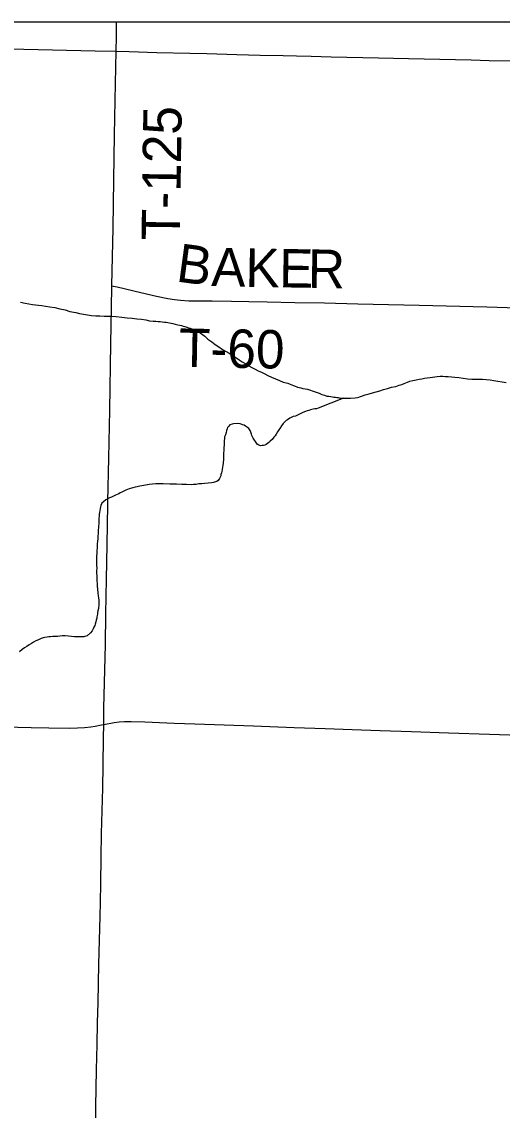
# Model space of a CAD drawing. Extents: x 2.1 to 73.9, y 4 to 26.
# Drawn here: x 43.618 to 43.974, y 24.1 to 24.905 of the extents above; entities that cross this region are included whole.
import ezdxf

# ---------------------------------------------------------------- set-up
doc = ezdxf.new("R2010")
doc.units = 0
for name, color, linetype in [('GM_X_County_Road', 7, 'Continuous'), ('GM_X_Minor_River', 7, 'Continuous'), ('GM_X_Township_Road', 7, 'Continuous'), ('GM_X_Township_Road_Text', 7, 'Continuous'), ('SH_Data', 7, 'Continuous')]:
    doc.layers.add(name, color=color, linetype=linetype)

msp = doc.modelspace()

# ---------------------------------------------------------------- linework, layer by layer
at = {"layer": 'GM_X_County_Road'}
for points in [[(43.16489, 24.39352), (43.19852, 24.39287), (43.21842, 24.39249), (43.24172, 24.39197), (43.25913, 24.3915), (43.2986, 24.39047), (43.31693, 24.39001), (43.36697, 24.38903), (43.40551, 24.38816), (43.44528, 24.38729), (43.47978, 24.38654), (43.4975, 24.38626), (43.53915, 24.38537), (43.60565, 24.38389), (43.62554, 24.3835), (43.6386, 24.38326), (43.65351, 24.38296), (43.65971, 24.38304), (43.66496, 24.38332), (43.66957, 24.38379), (43.67292, 24.38436), (43.67746, 24.38531), (43.67911, 24.38566)], [(43.67911, 24.38566), (43.68693, 24.38705), (43.69061, 24.38748), (43.69462, 24.38771), (43.69957, 24.38775), (43.70951, 24.38754), (43.73125, 24.38671), (43.74648, 24.3862), (43.78996, 24.38451), (43.8201, 24.38351), (43.84309, 24.38263), (43.86297, 24.38194), (43.88378, 24.38119), (43.90708, 24.38035), (43.93443, 24.37951), (43.96487, 24.37841), (44.00175, 24.37712), (44.04068, 24.37576), (44.05496, 24.37523), (44.07206, 24.37468), (44.0938, 24.3739), (44.13543, 24.37248), (44.17551, 24.37109), (44.18536, 24.37079)]]:
    msp.add_lwpolyline(points, dxfattribs=at)
at = {"layer": 'GM_X_Minor_River'}
for points in [[(43.61753, 24.69783), (43.62094, 24.6972), (43.62378, 24.69659), (43.62644, 24.69617), (43.62872, 24.69575), (43.6308, 24.69552), (43.63327, 24.6953), (43.63593, 24.69487), (43.63934, 24.69444), (43.64295, 24.69381), (43.64674, 24.69299), (43.65053, 24.69217), (43.65393, 24.69097), (43.65849, 24.69014), (43.66133, 24.68953), (43.66417, 24.68891), (43.66702, 24.68848), (43.67005, 24.68806), (43.67328, 24.68781), (43.67632, 24.68777), (43.67936, 24.68753), (43.68222, 24.68748), (43.68526, 24.68743), (43.6883, 24.68719), (43.69266, 24.68674), (43.69646, 24.6863), (43.70026, 24.68605), (43.70368, 24.68562), (43.70709, 24.68518), (43.71032, 24.68475), (43.71297, 24.68414), (43.71563, 24.6839), (43.71772, 24.68387), (43.71943, 24.68365), (43.72095, 24.68344), (43.72247, 24.68322), (43.72417, 24.68301), (43.72532, 24.68299), (43.73024, 24.68196), (43.73214, 24.68155), (43.73403, 24.68114), (43.73555, 24.68092), (43.73669, 24.68053), (43.73801, 24.68012), (43.73915, 24.67992), (43.74066, 24.67932), (43.7418, 24.67892), (43.74312, 24.67852), (43.74426, 24.67812), (43.74539, 24.67773), (43.74671, 24.67714), (43.74785, 24.67655), (43.74917, 24.67596), (43.75049, 24.67517), (43.75218, 24.67401), (43.75406, 24.67265), (43.75612, 24.67052), (43.75913, 24.66857), (43.76157, 24.66664), (43.7644, 24.66488), (43.76703, 24.66294), (43.76967, 24.66138), (43.77212, 24.66001), (43.774, 24.65884), (43.77569, 24.65767), (43.77758, 24.6565), (43.77946, 24.65514), (43.78153, 24.65378), (43.78436, 24.65221), (43.78662, 24.65084), (43.78888, 24.64948), (43.79114, 24.6483), (43.79359, 24.64712), (43.79586, 24.64613), (43.79831, 24.64477), (43.80076, 24.64359), (43.80341, 24.6424), (43.80624, 24.64103), (43.80926, 24.63984), (43.8121, 24.63865), (43.81551, 24.63784), (43.81777, 24.63685), (43.82042, 24.63586), (43.82269, 24.63506), (43.82496, 24.63446), (43.82667, 24.63405), (43.82837, 24.63364), (43.82989, 24.63343)], [(43.82989, 24.63343), (43.83576, 24.63162), (43.83859, 24.63044), (43.84067, 24.62964), (43.84256, 24.62904), (43.84427, 24.62845), (43.84579, 24.62823), (43.8473, 24.62802), (43.84844, 24.62781), (43.84958, 24.6276), (43.85072, 24.62758), (43.85167, 24.62738), (43.85262, 24.62736), (43.85357, 24.62716), (43.85489, 24.62695), (43.8566, 24.62692), (43.85775, 24.6269), (43.85908, 24.62688), (43.86022, 24.62686), (43.86193, 24.62683), (43.86536, 24.62716), (43.86707, 24.62732), (43.86803, 24.62768), (43.86917, 24.62805), (43.8707, 24.62859), (43.87262, 24.62932), (43.87567, 24.63003), (43.87816, 24.63075), (43.88083, 24.63166), (43.88351, 24.63237), (43.88618, 24.63328), (43.88924, 24.63399), (43.89229, 24.63489), (43.89535, 24.6356), (43.89784, 24.63651), (43.89994, 24.63705), (43.90147, 24.6376), (43.90396, 24.6387), (43.90568, 24.63943), (43.90797, 24.63996), (43.91045, 24.64049), (43.91274, 24.64083), (43.91465, 24.64118), (43.91655, 24.64153), (43.91865, 24.64188), (43.92075, 24.64203), (43.92265, 24.64238), (43.92437, 24.64274), (43.92589, 24.6429), (43.92818, 24.64306), (43.93008, 24.64302), (43.93198, 24.64299), (43.93426, 24.64277), (43.93673, 24.64254), (43.9392, 24.64231), (43.94205, 24.64207), (43.94527, 24.64164), (43.9485, 24.64121), (43.95173, 24.64097), (43.95515, 24.64091), (43.95952, 24.64084), (43.96237, 24.64061), (43.96522, 24.64037), (43.96807, 24.63994), (43.97091, 24.63933), (43.97414, 24.6389), (43.97717, 24.63847)], [(43.8566, 24.62692), (43.83785, 24.61943), (43.8367, 24.61907), (43.83537, 24.6189), (43.83422, 24.61873), (43.83327, 24.61855), (43.83212, 24.61819), (43.83098, 24.61783), (43.82964, 24.61747), (43.82849, 24.61692), (43.82658, 24.61619), (43.82504, 24.61546), (43.8237, 24.61472), (43.82255, 24.61436), (43.82102, 24.61362), (43.81949, 24.61327), (43.81796, 24.61253), (43.817, 24.61197), (43.81508, 24.61087), (43.81412, 24.61031), (43.81199, 24.60807), (43.81083, 24.60637), (43.80946, 24.6045), (43.80888, 24.60355), (43.80771, 24.60186), (43.80693, 24.60036), (43.80596, 24.59904), (43.80499, 24.59792), (43.80382, 24.59642), (43.80247, 24.59511), (43.80131, 24.59418), (43.80035, 24.59324), (43.79939, 24.59269), (43.79843, 24.59213), (43.79747, 24.59177), (43.79652, 24.59178), (43.79519, 24.59162), (43.79387, 24.59221), (43.79273, 24.5928), (43.79143, 24.59472), (43.79069, 24.59587), (43.78976, 24.59721), (43.78921, 24.59836), (43.78884, 24.59932), (43.78867, 24.60027), (43.78812, 24.6018), (43.78757, 24.60295), (43.78664, 24.60448), (43.7857, 24.60507), (43.7842, 24.60623), (43.78307, 24.60682), (43.78193, 24.60722), (43.78099, 24.60761), (43.78004, 24.60782), (43.77833, 24.60804), (43.7751, 24.6079), (43.77414, 24.60772), (43.77261, 24.60718), (43.77165, 24.60624), (43.77087, 24.60512), (43.77047, 24.60417), (43.77007, 24.60285), (43.76967, 24.60153), (43.76926, 24.59963), (43.76867, 24.59831), (43.76845, 24.59679), (43.76843, 24.59546), (43.76842, 24.59452), (43.76821, 24.59319), (43.76819, 24.59186), (43.76816, 24.59053), (43.76814, 24.5892), (43.76812, 24.58787), (43.76791, 24.58635), (43.76789, 24.58502), (43.76787, 24.58369), (43.76785, 24.58237), (43.76782, 24.58104), (43.76761, 24.57971), (43.76759, 24.57857), (43.76739, 24.57743), (43.76717, 24.57592), (43.76695, 24.57402), (43.76655, 24.5727), (43.76634, 24.57156), (43.76594, 24.57043), (43.76574, 24.56948), (43.76534, 24.56853), (43.76476, 24.56741), (43.76378, 24.5659), (43.76282, 24.56535), (43.76186, 24.56498), (43.76053, 24.56462), (43.75919, 24.56426), (43.75367, 24.56378), (43.75176, 24.56362), (43.74967, 24.56347), (43.74757, 24.56312), (43.74567, 24.56296), (43.74376, 24.5628), (43.74034, 24.56305)], [(43.74034, 24.56305), (43.73692, 24.5631), (43.73293, 24.56317), (43.72817, 24.56324), (43.72304, 24.56351), (43.71772, 24.56341), (43.71276, 24.56292), (43.70876, 24.56222), (43.7059, 24.5617), (43.7038, 24.56135), (43.70246, 24.56099), (43.70075, 24.56064), (43.6996, 24.56028), (43.69807, 24.55993), (43.69673, 24.55938), (43.69558, 24.55882), (43.69443, 24.55827), (43.69348, 24.55791), (43.69252, 24.55735), (43.69137, 24.5568), (43.69022, 24.55625), (43.68907, 24.5557), (43.68792, 24.55515), (43.68639, 24.55441), (43.68485, 24.55368), (43.68332, 24.55313), (43.68178, 24.55221), (43.68064, 24.55165), (43.6789, 24.55016), (43.67774, 24.54923), (43.67696, 24.54753), (43.67675, 24.5464), (43.67654, 24.54526), (43.67633, 24.54393), (43.67592, 24.54242), (43.67571, 24.54109), (43.67569, 24.53957), (43.67548, 24.53806), (43.67545, 24.53635), (43.67542, 24.53464), (43.67514, 24.52875), (43.67492, 24.52686), (43.67488, 24.52477), (43.67466, 24.52287), (43.67464, 24.52116), (43.67441, 24.51907), (43.67418, 24.51642), (43.67414, 24.51395), (43.67392, 24.51205), (43.67389, 24.51034), (43.67386, 24.50825), (43.67382, 24.50559), (43.67378, 24.50332), (43.67394, 24.50122), (43.67391, 24.49932), (43.67388, 24.49743), (43.67404, 24.49571), (43.67401, 24.49381), (43.67398, 24.49191), (43.67433, 24.48982), (43.6743, 24.48773), (43.67465, 24.48582), (43.67479, 24.48278), (43.67514, 24.48069), (43.6753, 24.47916), (43.67547, 24.47764), (43.67545, 24.47631), (43.67543, 24.47536), (43.67542, 24.47441), (43.6754, 24.47327), (43.67519, 24.47232), (43.67518, 24.47137), (43.67477, 24.46967), (43.67456, 24.46835), (43.67454, 24.46721), (43.67434, 24.46626), (43.67413, 24.46531), (43.67392, 24.46418), (43.67352, 24.46266), (43.67331, 24.46153), (43.6729, 24.45982), (43.6725, 24.45869), (43.67192, 24.45756), (43.67132, 24.45624), (43.67054, 24.45473), (43.66938, 24.45342), (43.66687, 24.45118), (43.66591, 24.45081), (43.66439, 24.45046), (43.66248, 24.45049), (43.66039, 24.45033), (43.65754, 24.45038), (43.65526, 24.45061), (43.65298, 24.45083), (43.6507, 24.45106), (43.64861, 24.45109), (43.64671, 24.45093), (43.6448, 24.45077), (43.64309, 24.45061), (43.64138, 24.45064), (43.63985, 24.45047)], [(43.63985, 24.45047), (43.63852, 24.4503), (43.63718, 24.45014), (43.63547, 24.44997), (43.63432, 24.44961), (43.63279, 24.44907), (43.63088, 24.44815), (43.62896, 24.44742), (43.62724, 24.44649), (43.6257, 24.44557), (43.62397, 24.44446), (43.62224, 24.44334), (43.62051, 24.44223), (43.61878, 24.44112), (43.61667, 24.43945)]]:
    msp.add_lwpolyline(points, dxfattribs=at)
at = {"layer": 'GM_X_Township_Road'}
for points in [[(43.68845, 24.88346), (43.68848, 24.89416), (43.68863, 24.90511)], [(43.18601, 24.89397), (43.19929, 24.89361), (43.22073, 24.89313), (43.26518, 24.89227), (43.28321, 24.89199), (43.31552, 24.89129), (43.36152, 24.89026), (43.41777, 24.88903), (43.45568, 24.88817), (43.48178, 24.88759), (43.51161, 24.88699), (43.52995, 24.8867), (43.54891, 24.8863), (43.5716, 24.88587), (43.62008, 24.8849), (43.67291, 24.88356), (43.68845, 24.88346)], [(43.6852, 24.70989), (43.6852, 24.71026), (43.68608, 24.7525), (43.68658, 24.78826), (43.68716, 24.82121), (43.6877, 24.847), (43.68818, 24.87155), (43.68845, 24.88346)], [(43.68845, 24.88346), (43.69805, 24.8832), (43.71855, 24.88251), (43.7428, 24.88193), (43.75554, 24.88156), (43.77761, 24.881), (43.79502, 24.88054), (43.81211, 24.88017), (43.82175, 24.87987), (43.83263, 24.87969), (43.84754, 24.87931), (43.88267, 24.87852), (43.90474, 24.87806), (43.95106, 24.87696), (43.96442, 24.87659), (43.98432, 24.87616)], [(43.68227, 24.55035), (43.68304, 24.58251), (43.68369, 24.61795), (43.68449, 24.66737), (43.68498, 24.69348), (43.6852, 24.70989)], [(43.6852, 24.70989), (43.68761, 24.70938), (43.68913, 24.70907), (43.70668, 24.70496), (43.71819, 24.70231), (43.72671, 24.70055), (43.73163, 24.69978), (43.73595, 24.6993), (43.74215, 24.69892), (43.74868, 24.69878), (43.75954, 24.69881), (43.77379, 24.69856), (43.78653, 24.69828), (43.8002, 24.69806), (43.82071, 24.69762), (43.84247, 24.69729), (43.86732, 24.69666), (43.91269, 24.6955), (43.96271, 24.69428), (44.00807, 24.69299)], [(43.67911, 24.38566), (43.67931, 24.39791), (43.68043, 24.44452), (43.68076, 24.46753), (43.68119, 24.49301), (43.68168, 24.5185), (43.68222, 24.54834), (43.68227, 24.55035)], [(43.66877, 23.87821), (43.66882, 23.88078), (43.66933, 23.90004), (43.66987, 23.92615), (43.67025, 23.9448), (43.67138, 23.99607), (43.67163, 24.00913), (43.672, 24.02591), (43.67275, 24.06631), (43.67329, 24.1033), (43.67385, 24.13033), (43.6742, 24.14898), (43.67454, 24.16514), (43.67491, 24.18006), (43.67558, 24.20834), (43.67642, 24.24377), (43.67665, 24.25402), (43.67692, 24.26831), (43.67729, 24.28727), (43.6776, 24.30498), (43.67839, 24.33855), (43.67865, 24.35565), (43.67895, 24.37554), (43.67911, 24.38566)]]:
    msp.add_lwpolyline(points, dxfattribs=at)
at = {"layer": 'SH_Data'}
msp.add_line((41.95853, 24.90511), (48.75853, 24.90511), dxfattribs=at)

# ---------------------------------------------------------------- texts
at = {"layer": 'GM_X_Township_Road_Text'}
for s, height, rotation, p in [('T-125', 0.028409, 89.18803, (43.73552, 24.74336)), ('B', 0.02841, 352.28388, (43.73206, 24.71322)), ('A', 0.02841, 358.58311, (43.75858, 24.70982)), ('K', 0.02841, 359.11504, (43.78386, 24.70919)), ('E', 0.02841, 359.11283, (43.80886, 24.70881)), ('R', 0.02841, 359.1101, (43.8301, 24.70848)), ('T-60', 0.028409, 358.9513, (43.73463, 24.65004))]:
    msp.add_text(s, height=height, rotation=rotation, dxfattribs=at).set_placement(p)

doc.saveas('drawing.dxf')
